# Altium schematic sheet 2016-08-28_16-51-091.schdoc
size 331 x 127 mm; SheetNumber: 1; SheetTotal: 1
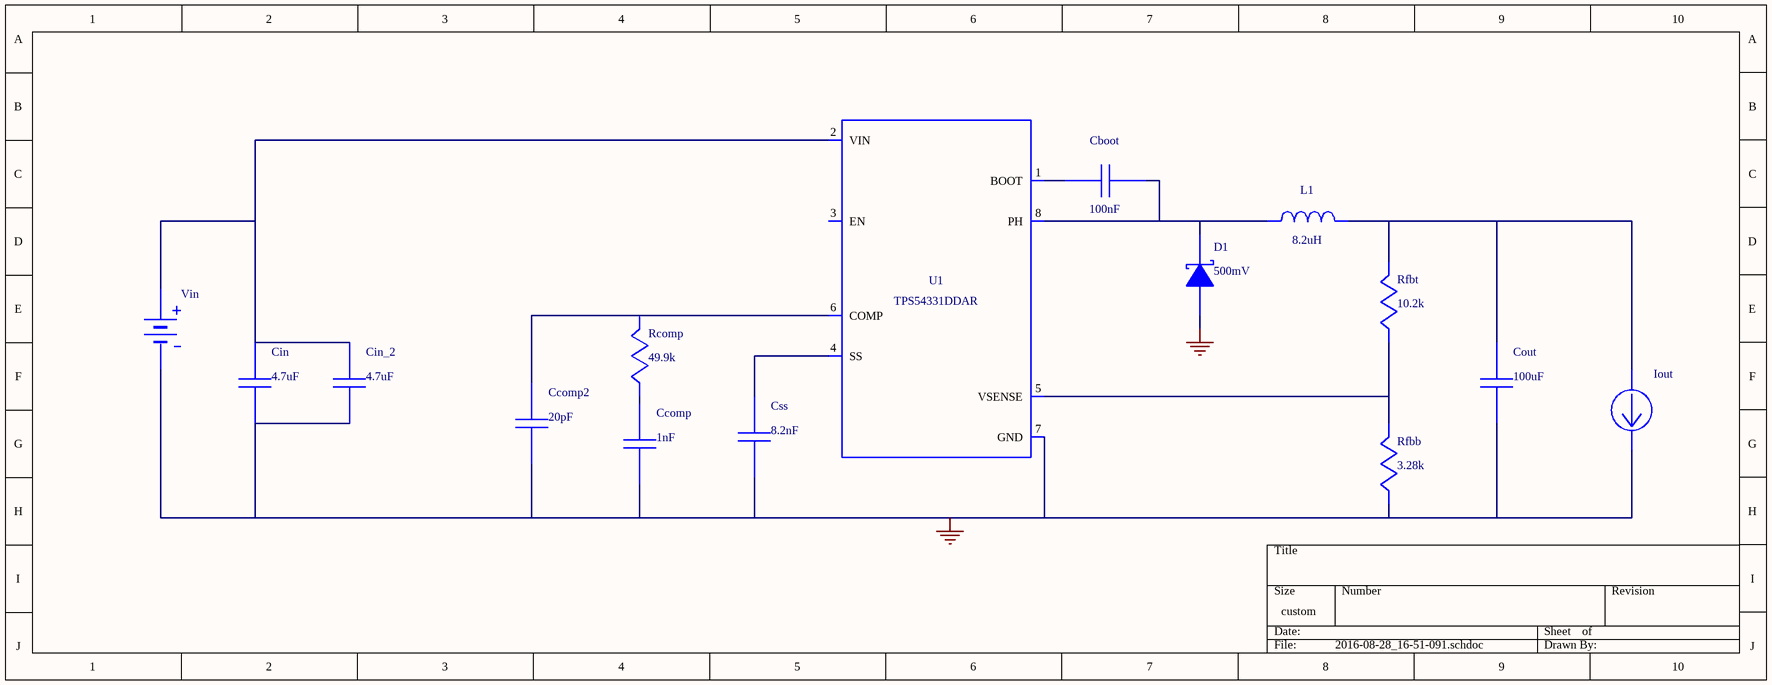
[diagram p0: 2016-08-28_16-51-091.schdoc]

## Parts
Cboot  value 100nF  (hidden comment: GRM155R61A104KA01D)
Ccomp  value 1nF  (hidden comment: CL21C102JBCNFNC)
Ccomp2  value 20pF  (hidden comment: CL21C200JBANNNC)
Cin  value 4.7uF  (hidden comment: GRM32ER71H475KA88L)
Cin_2  value 4.7uF  (hidden comment: GRM32ER71H475KA88L)
Cout  value 100uF  (hidden comment: GRM31CR60J107ME39L)
Css  value 8.2nF  (hidden comment: GRM033R61A822KA01D)
D1  value 500mV  (hidden comment: B340A-13-F)
Iout  WB_CURRENT_LOAD  (value not drawn)
L1  value 8.2uH  (hidden comment: SRN8040-8R2Y)
Rcomp  value 49.9k  (hidden comment: CRCW040249K9FKED)
Rfbb  value 3.28k  (hidden comment: RT0805BRD073K28L)
Rfbt  value 10.2k  (hidden comment: CRCW040210K2FKED)
U1  TPS54331DDAR
Vin  WB_BATTERY  (value not drawn)

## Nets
0: Ccomp.2 Ccomp2.2 Cin.2 Cin_2.2 Cout.2 Css.2 D1.2(A) Iout.2(-) Rfbb.2 U1.7(GND) U1.9(ETPAD) Vin.2(-)
NetCboot_1: Cboot.1 U1.1(BOOT)
NetCboot_2: Cboot.2 D1.1(K) L1.2 U1.8(PH)
NetCcomp2_1: Ccomp2.1 Rcomp.1 U1.6(COMP)
NetCcomp_1: Ccomp.1 Rcomp.2
NetCin_1: Cin.1 Cin_2.1 U1.2(VIN) Vin.1(+)
NetCout_1: Cout.1 Iout.1(+) L1.1 Rfbt.1
NetCss_1: Css.1 U1.4(SS)
NetRfbb_1: Rfbb.1 Rfbt.2 U1.5(VSENSE)

Not connected (* = marked no-connect by the designer): U1 3(EN)

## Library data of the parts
Cboot = GRM155R61A104KA01D: GRM155R61A104KA0; Manufacturer Name: MuRata
Ccomp = CL21C102JBCNFNC: Manufacturer Name: Samsung Electro-Mechanics
Ccomp2 = CL21C200JBANNNC: Manufacturer Name: Samsung Electro-Mechanics
Cin Cin_2 = GRM32ER71H475KA88L: GRM32ER71H475KA8; Manufacturer Name: MuRata
Cout = GRM31CR60J107ME39L: GRM31CR60J107ME3; Manufacturer Name: MuRata
Css = GRM033R61A822KA01D: GRM033R61A822KA0; Manufacturer Name: MuRata
D1 = B340A-13-F: Manufacturer Name: Diodes Inc.
L1 = SRN8040-8R2Y: Manufacturer Name: Bourns
Rcomp = CRCW040249K9FKED: Manufacturer Name: Vishay-Dale
Rfbb = RT0805BRD073K28L: Manufacturer Name: Yageo America
Rfbt = CRCW040210K2FKED: Manufacturer Name: Vishay-Dale
U1 = TPS54331DDAR: Manufacturer Name: Texas Instruments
